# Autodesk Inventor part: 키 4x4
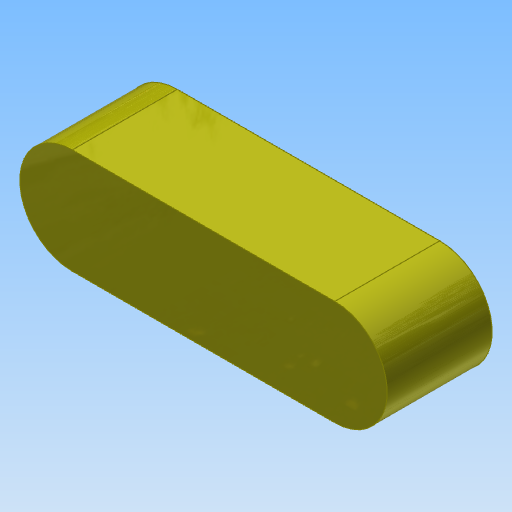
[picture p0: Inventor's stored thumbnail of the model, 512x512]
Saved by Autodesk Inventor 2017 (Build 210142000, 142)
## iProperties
Created: 2014-10
Part Number: 키 4x4
Document SubType Name: Modeling
Designer: KYOUNG IL JANG
Density: 7.86 g/cm^3
Mass: 1.65269 g
Surface Area: 2.35398 cm^2
Volume: 0.210265 cm^3
Material: 강철, 연강
Appearance: 노란색
Author: SeoGD™ [www.esajin.kr]
Revision Number: 1
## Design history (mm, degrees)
sketch "스케치1"
  geometry: L1 (-5, -2)-(5, -2); L2 (5, 2)-(-5, 2); A1 r 2 centre (5, 0) between (5, -2) and (5, 2); A2 r 2 centre (-5, 0) between (-5, 2) and (-5, -2); 2 further points
  constraints: 4 end point, 4 point on circle, 4 tangent, 2 centre point, 1 horizontal, 1 horizontal alignment, 1 midpoint, 1 parallel, 1 vertical alignment
  dimensions: "d0" = 4 distance between parallel lines of L1 L2; "d1" = 14 dimension on A1 A2
extrude "돌출1" new body sketch "스케치1" stored distance "d2" = 4; taper "d3" = 0 deg
node "솔리드1"
